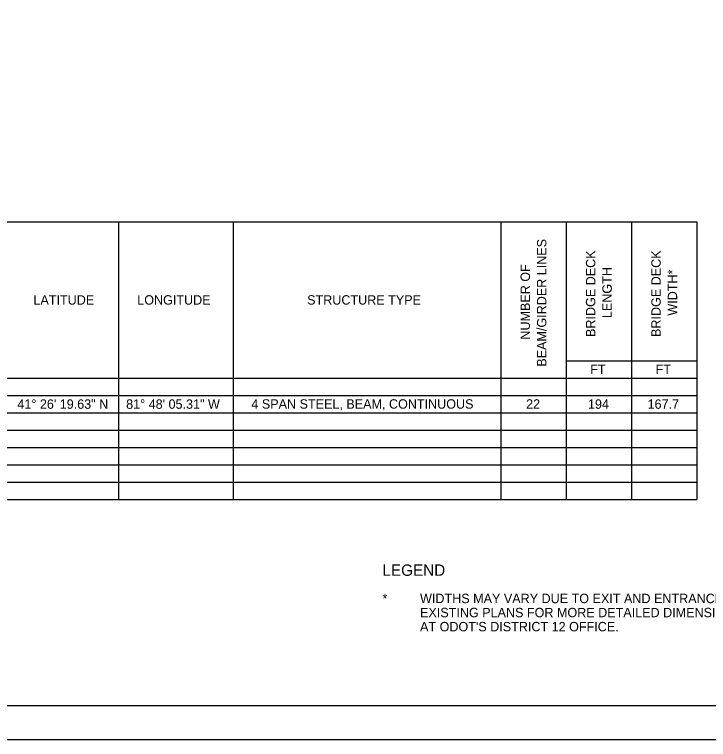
# Model space of a CAD drawing. Extents: x 0 to 680, y 0 to 440.
# Drawn here: x 336.3 to 543, y 0 to 216.1 of the extents above; entities that cross this region are included whole.
import ezdxf

# ---------------------------------------------------------------- set-up
doc = ezdxf.new("R2010")
doc.units = 0
for name, color, linetype in [('DR_P_Text', 7, 'Continuous'), ('SH_Border', 7, 'Continuous'), ('SH_Cut_Line', 7, 'Continuous'), ('SH_Text', 7, 'Continuous')]:
    doc.layers.add(name, color=color, linetype=linetype)

msp = doc.modelspace()

# ---------------------------------------------------------------- linework, layer by layer
at = {"layer": 'SH_Border'}
msp.add_lwpolyline([(30, 430), (670, 430), (670, 10), (30, 10)], close=True, dxfattribs=at)
at = {"layer": 'SH_Cut_Line'}
msp.add_lwpolyline([(0, 0), (680, 0), (680, 440), (0, 440)], close=True, dxfattribs=at)
at = {"layer": 'SH_Text'}
for p, q in [((113.49, 154.3), (539.58, 154.3)), ((367.32, 154.3), (367.32, 71.51)), ((401.41, 154.3), (401.41, 71.51)), ((481.15, 154.3), (481.15, 71.51)), ((500.62, 154.3), (500.62, 71.51)), ((520.1, 154.3), (520.1, 71.51)), ((539.58, 154.3), (539.58, 71.51)), ((500.62, 112.9), (539.58, 112.9)), ((113.49, 107.73), (539.58, 107.73)), ((113.49, 102.56), (539.58, 102.56)), ((113.49, 97.38), (539.58, 97.38)), ((113.49, 92.21), (539.58, 92.21)), ((113.49, 87.04), (539.58, 87.04)), ((113.49, 81.86), (539.58, 81.86)), ((113.49, 76.69), (539.58, 76.69)), ((113.49, 71.51), (539.58, 71.51))]:
    msp.add_line(p, q, dxfattribs=at)

# ---------------------------------------------------------------- texts
at = {"layer": 'DR_P_Text'}
for s, height, p in [('LEGEND', 3.4, (445.9, 48.78)), ('*', 2.8, (445.9, 40.64)), ('WIDTHS MAY VARY DUE TO EXIT AND ENTRANCE RAMPS ON THE STRUCTURE. SEE', 2.8, (457.1, 40.64)), ('EXISTING PLANS FOR MORE DETAILED DIMENSIONS. THESE PLANS CAN BE VIEWED', 2.8, (457.1, 36.44)), ("AT ODOT'S DISTRICT 12 OFFICE.", 2.8, (457.1, 32.24))]:
    msp.add_text(s, height=height, dxfattribs=at).set_placement(p)
at = {"layer": 'SH_Text'}
for s, p in [('BEAM/GIRDER LINES', (494.73, 111.11)), ('BRIDGE DECK ', (509.31, 119.97)), ('BRIDGE DECK ', (528.79, 119.97)), ('NUMBER OF ', (489.83, 119.18)), ('LENGTH', (514.21, 125.6)), ('WIDTH*', (533.69, 126.33))]:
    msp.add_text(s, height=2.8, rotation=90, dxfattribs=at).set_placement(p)
for s, p in [('LATITUDE', (341.94, 129.61)), ('LONGITUDE', (372.86, 129.61)), ('STRUCTURE TYPE', (423.47, 129.61)), ('FT', (507.78, 108.95)), ('FT', (527.26, 108.95)), ('41° 26\' 19.63" N', (337.15, 98.57)), ('81° 48\' 05.31" W', (369.56, 98.57)), ('4 SPAN STEEL, BEAM, CONTINUOUS', (406.85, 98.6)), ('22', (488.7, 98.6)), ('194', (507.12, 98.57)), ('167.7', (524.87, 98.57))]:
    msp.add_text(s, height=2.8, dxfattribs=at).set_placement(p)

doc.saveas('drawing.dxf')
